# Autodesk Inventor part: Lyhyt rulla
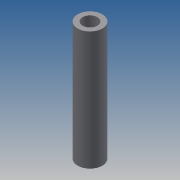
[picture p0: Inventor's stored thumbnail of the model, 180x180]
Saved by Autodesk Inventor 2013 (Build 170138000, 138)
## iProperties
Created: 2013-08
Part Number: Lyhyt rulla
Material: Generic
Document SubType Name: Modeling
Designer: Reko Tuppurainen
Density: 1 g/cm^3
Author: Reko Tuppurainen
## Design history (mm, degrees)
sketch "Sketch1"
  geometry: C1 r 10 at (0, 0); 1 further point
  constraints: 1 centre point, 1 coincident
  dimensions: "d0" = 20 diameter of C1
extrude "Extrusion1" new body sketch "Sketch1" distance "d1" = 96; taper "d2" = 0 deg
sketch "Sketch2"
  geometry: C1 r 10 at (0, 0) reference; C2 r 6 at (0, 0)
  constraints: 1 centre point, 1 coincident
  dimensions: "d3" = 12 diameter of C2
extrude "Extrusion2" cut sketch "Sketch2" stored distance "d4" = 96; taper "d5" = 0 deg
body "Solid1"
